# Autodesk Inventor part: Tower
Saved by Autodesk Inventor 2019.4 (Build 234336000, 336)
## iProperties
Created: 2020-04
Part Number: Tower
Material: Generic
Document SubType Name: Modeling
Designer: Administrator
Density: 1 g/cm^3
Appearance: Default
Title: Tower v1
Author: Administrator
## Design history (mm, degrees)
feature "Body1"
body "Solid1"
